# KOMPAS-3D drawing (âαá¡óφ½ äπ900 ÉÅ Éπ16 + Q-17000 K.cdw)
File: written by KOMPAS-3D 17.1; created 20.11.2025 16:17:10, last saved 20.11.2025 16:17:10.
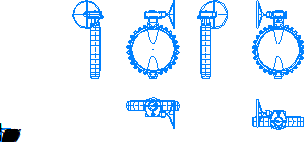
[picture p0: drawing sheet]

Sheet 1: A4, portrait

Title block, sheet 1: name: Гранвэл Ду900; material: Сталь 10  ГОСТ 1050-88; mass: 905,26; sheets: 1; sheet format: A4

Views: Проекционный вид 2, Проекционный вид 3, Проекционный вид 5
Referenced files in \\adlc.lan\data\АДЛ_ПКД\3D-модели\ADL production\Дисковые поворотные затворы ГРАНВЭЛ\с резьбовыми проушинами с китайским редуктором Ру 16\KOMPAS 3D\: Гранвэл Ду900 РП Ру16 + Q-17000 K.m3d
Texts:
  Andrey
  АДЛ
Dimensions and other numbers on the sheet: 1:1; 1; 905,26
